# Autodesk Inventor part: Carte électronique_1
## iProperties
Created: 2010-07
Part Number: Carte électronique_1
Document SubType Name: Modeling
Designer: eric
Density: 1 g/cm^3
Author: eric
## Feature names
1. Base1
